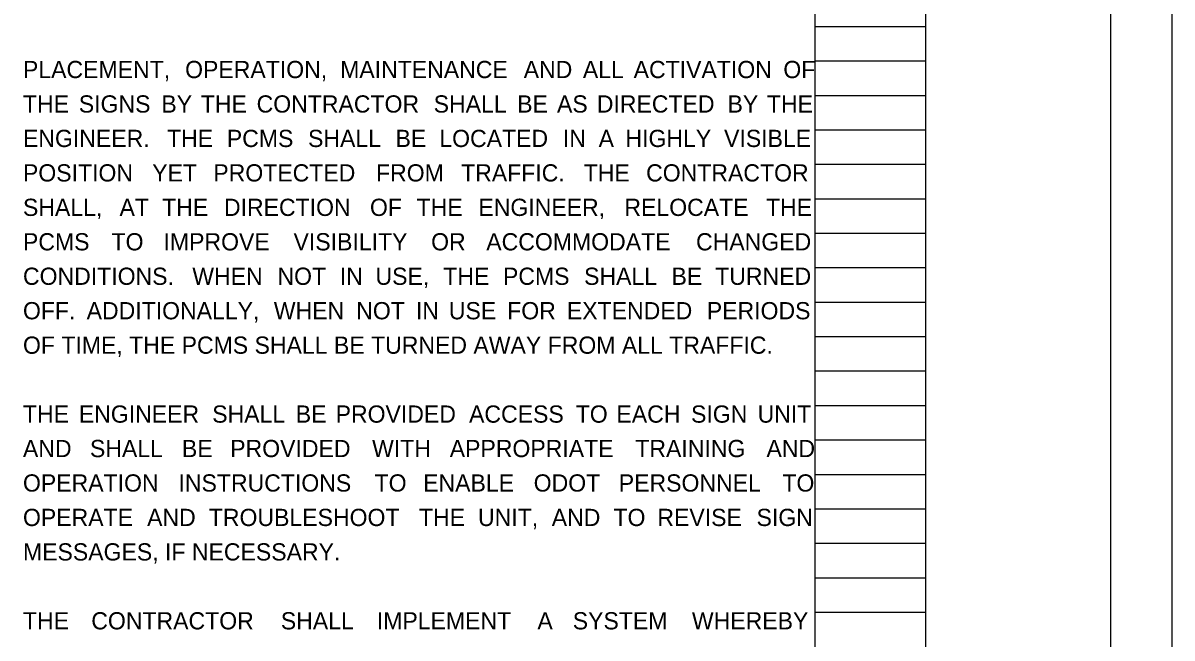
# Model space of a CAD drawing. Extents: x 0 to 34, y 0 to 22.
# Drawn here: x 24.66 to 34, y 5.25 to 10.25 of the extents above; entities that cross this region are included whole.
import ezdxf

# ---------------------------------------------------------------- set-up
doc = ezdxf.new("R2010")
doc.units = 0
for name, color, linetype in [('SH_Border', 7, 'Continuous'), ('SH_Cut_Line', 7, 'Continuous'), ('SH_Data', 7, 'Continuous'), ('SH_Text', 7, 'Continuous')]:
    doc.layers.add(name, color=color, linetype=linetype)

msp = doc.modelspace()

# ---------------------------------------------------------------- linework, layer by layer
at = {"layer": 'SH_Border'}
msp.add_line((32, 0.5), (32, 21.5), dxfattribs=at)
msp.add_lwpolyline([(1.5, 21.5), (33.5, 21.5), (33.5, 0.5), (1.5, 0.5)], close=True, dxfattribs=at)
at = {"layer": 'SH_Cut_Line'}
msp.add_lwpolyline([(0, 0), (34, 0), (34, 22), (0, 22)], close=True, dxfattribs=at)
at = {"layer": 'SH_Data'}
for p, q in [((31.1, 0.98), (31.1, 21.14)), ((32, 0.98), (32, 21.14)), ((31.1, 10.22), (32, 10.22)), ((31.1, 9.94), (32, 9.94)), ((31.1, 9.66), (32, 9.66)), ((31.1, 9.38), (32, 9.38)), ((31.1, 9.1), (32, 9.1)), ((31.1, 8.82), (32, 8.82)), ((31.1, 8.54), (32, 8.54)), ((31.1, 8.26), (32, 8.26)), ((31.1, 7.98), (32, 7.98)), ((31.1, 7.7), (32, 7.7)), ((31.1, 7.42), (32, 7.42)), ((31.1, 7.14), (32, 7.14)), ((31.1, 6.86), (32, 6.86)), ((31.1, 6.58), (32, 6.58)), ((31.1, 6.3), (32, 6.3)), ((31.1, 6.02), (32, 6.02)), ((31.1, 5.74), (32, 5.74)), ((31.1, 5.46), (32, 5.46))]:
    msp.add_line(p, q, dxfattribs=at)

# ---------------------------------------------------------------- texts
at = {"layer": 'SH_Text'}
for s, p in [('PLACEMENT, ', (24.66, 9.8)), ('OPERATION, ', (25.9781, 9.8)), ('MAINTENANCE ', (27.2382, 9.8)), ('AND ', (28.7302, 9.8)), ('ALL ', (29.2113, 9.8)), ('ACTIVATION ', (29.6238, 9.8)), ('OF ', (30.8405, 9.8)), ('THE ', (24.66, 9.52)), ('SIGNS ', (25.1139, 9.52)), ('BY ', (25.7852, 9.52)), ('THE ', (26.1053, 9.52)), ('CONTRACTOR ', (26.5592, 9.52)), ('SHALL ', (27.9985, 9.52)), ('BE ', (28.6773, 9.52)), ('AS ', (29.0009, 9.52)), ('DIRECTED ', (29.3245, 9.52)), ('BY ', (30.387, 9.52)), ('THE ', (30.7071, 9.52)), ('ENGINEER. ', (24.66, 9.24)), ('THE ', (25.831, 9.24)), ('PCMS ', (26.3172, 9.24)), ('SHALL ', (26.9773, 9.24)), ('BE ', (27.6884, 9.24)), ('LOCATED ', (28.0443, 9.24)), ('IN ', (29.0487, 9.24)), ('A ', (29.3392, 9.24)), ('HIGHLY ', (29.5573, 9.24)), ('VISIBLE ', (30.359, 9.24)), ('POSITION ', (24.66, 8.96)), ('YET ', (25.7108, 8.96)), ('PROTECTED ', (26.2073, 8.96)), ('FROM ', (27.5298, 8.96)), ('TRAFFIC. ', (28.2217, 8.96)), ('THE ', (29.218, 8.96)), ('CONTRACTOR ', (29.7253, 8.96)), ('SHALL, ', (24.66, 8.68)), ('AT ', (25.445, 8.68)), ('THE ', (25.7914, 8.68)), ('DIRECTION ', (26.2937, 8.68)), ('OF ', (27.4805, 8.68)), ('THE ', (27.8596, 8.68)), ('ENGINEER, ', (28.3619, 8.68)), ('RELOCATE ', (29.5489, 8.68)), ('THE ', (30.6998, 8.68)), ('PCMS ', (24.66, 8.4)), ('TO ', (25.3798, 8.4)), ('IMPROVE ', (25.8025, 8.4)), ('VISIBILITY ', (26.8593, 8.4)), ('OR ', (27.9779, 8.4)), ('ACCOMMODATE ', (28.4259, 8.4)), ('CHANGED ', (30.131, 8.4)), ('CONDITIONS. ', (24.66, 8.12)), ('WHEN ', (26.0366, 8.12)), ('NOT ', (26.7285, 8.12)), ('IN ', (27.2357, 8.12)), ('USE, ', (27.5255, 8.12)), ('THE ', (28.0763, 8.12)), ('PCMS ', (28.5618, 8.12)), ('SHALL ', (29.2212, 8.12)), ('BE ', (29.9317, 8.12)), ('TURNED ', (30.2869, 8.12)), ('OFF. ', (24.66, 7.84)), ('ADDITIONALLY, ', (25.1776, 7.84)), ('WHEN ', (26.6992, 7.84)), ('NOT ', (27.369, 7.84)), ('IN ', (27.854, 7.84)), ('USE ', (28.1217, 7.84)), ('FOR ', (28.5961, 7.84)), ('EXTENDED ', (29.0811, 7.84)), ('PERIODS ', (30.2186, 7.84)), ('OF TIME, THE PCMS SHALL BE TURNED AWAY FROM ALL TRAFFIC.', (24.66, 7.56)), ('THE ', (24.66, 7)), ('ENGINEER ', (25.1141, 7)), ('SHALL ', (26.1986, 7)), ('BE ', (26.8776, 7)), ('PROVIDED ', (27.2014, 7)), ('ACCESS ', (28.286, 7)), ('TO ', (29.1533, 7)), ('EACH ', (29.4842, 7)), ('SIGN ', (30.0905, 7)), ('UNIT ', (30.6316, 7)), ('AND ', (24.66, 6.72)), ('SHALL ', (25.2045, 6.72)), ('BE ', (25.9521, 6.72)), ('PROVIDED ', (26.3446, 6.72)), ('WITH ', (27.4978, 6.72)), ('APPROPRIATE ', (28.1289, 6.72)), ('TRAINING ', (29.6374, 6.72)), ('AND ', (30.7035, 6.72)), ('OPERATION ', (24.66, 6.44)), ('INSTRUCTIONS ', (25.9243, 6.44)), ('TO ', (27.5181, 6.44)), ('ENABLE ', (27.9128, 6.44)), ('ODOT ', (28.8114, 6.44)), ('PERSONNEL ', (29.5031, 6.44)), ('TO ', (30.8329, 6.44)), ('OPERATE ', (24.66, 6.16)), ('AND ', (25.6691, 6.16)), ('TROUBLESHOOT ', (26.1708, 6.16)), ('THE ', (27.879, 6.16)), ('UNIT, ', (28.3589, 6.16)), ('AND ', (28.9582, 6.16)), ('TO ', (29.4599, 6.16)), ('REVISE ', (29.8167, 6.16)), ('SIGN ', (30.6229, 6.16)), ('MESSAGES, IF NECESSARY.', (24.66, 5.88)), ('THE ', (24.66, 5.32)), ('CONTRACTOR ', (25.2153, 5.32)), ('SHALL ', (26.7561, 5.32)), ('IMPLEMENT ', (27.5363, 5.32)), ('A ', (28.8416, 5.32)), ('SYSTEM ', (29.1289, 5.32)), ('WHEREBY ', (30.0974, 5.32))]:
    msp.add_text(s, height=0.14, dxfattribs=at).set_placement(p)

doc.saveas('drawing.dxf')
